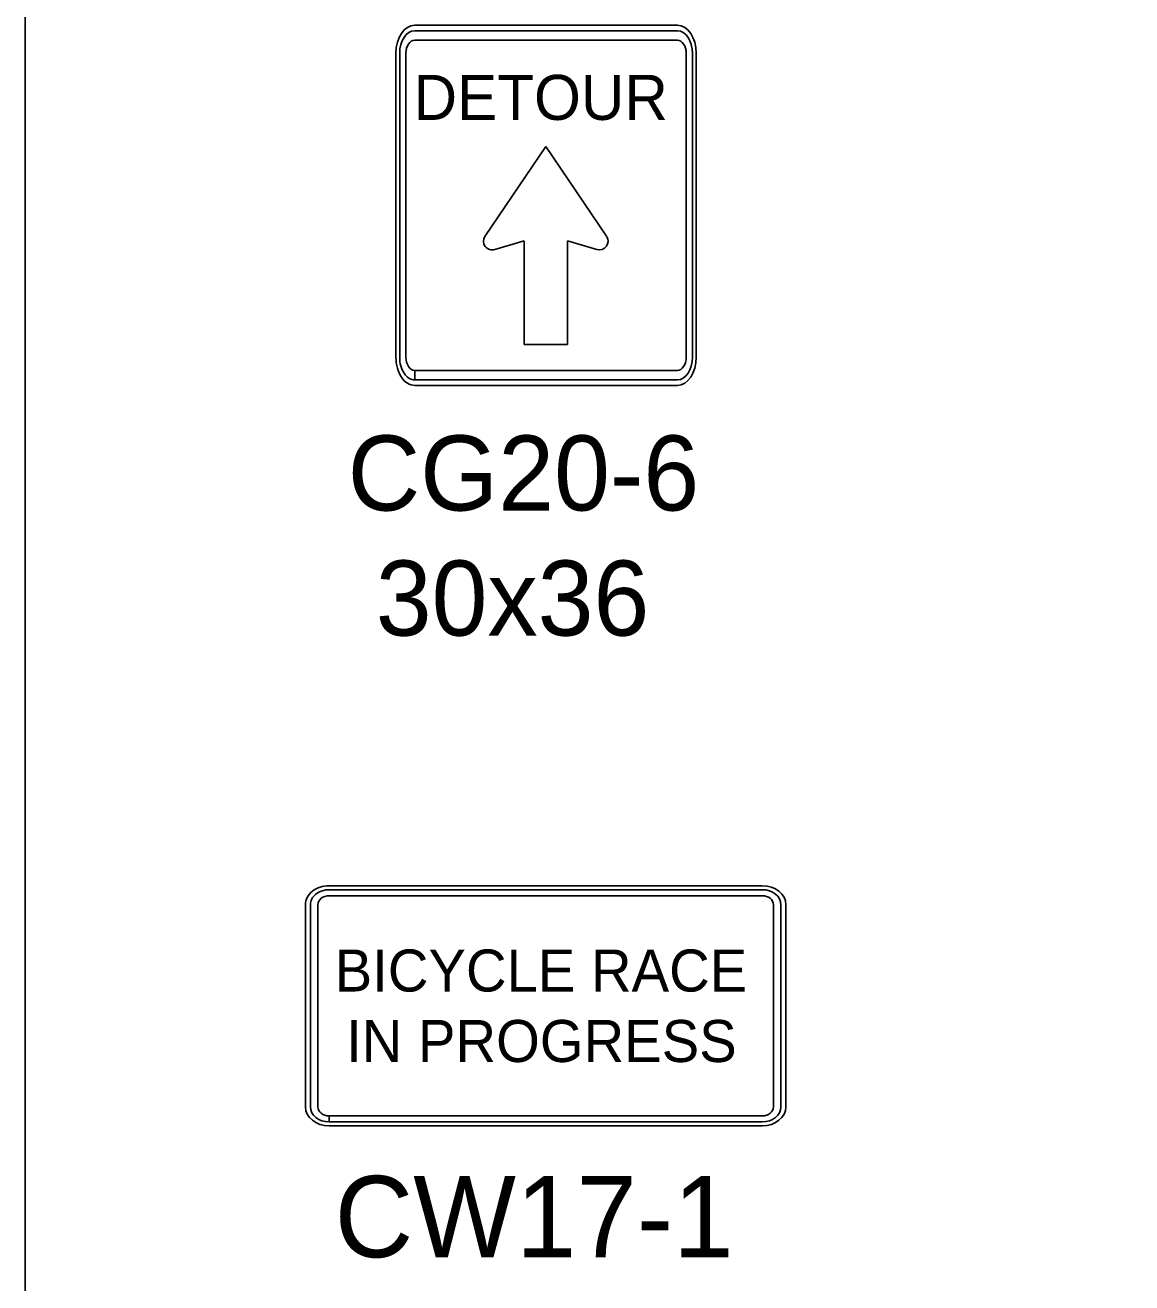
# Model space of a CAD drawing. Extents: x 1458 to 4498, y 17709 to 24109.
# Drawn here: x 1458.4 to 1679.5, y 21192.9 to 21444.2 of the extents above; entities that cross this region are included whole.
import ezdxf

# ---------------------------------------------------------------- set-up
doc = ezdxf.new("R2010")
doc.units = 0
doc.layers.add('P_TRAF_TCP_General', color=7, linetype='Continuous')

msp = doc.modelspace()

# ---------------------------------------------------------------- linework, layer by layer
at = {"layer": 'P_TRAF_TCP_General'}
for p, q in [((1588.72, 21444.19), (1536.24, 21444.19)), ((1588.72, 21443.06), (1536.24, 21443.06)), ((1588.72, 21443.06), (1536.24, 21443.06)), ((1536.24, 21441.19), (1588.72, 21441.19)), ((1532.49, 21438.57), (1532.49, 21377.84)), ((1533.24, 21438.57), (1533.24, 21377.84)), ((1533.24, 21438.57), (1533.24, 21377.84)), ((1534.49, 21377.84), (1534.49, 21438.57)), ((1590.47, 21438.57), (1590.47, 21377.84)), ((1591.72, 21377.84), (1591.72, 21438.57)), ((1591.72, 21377.84), (1591.72, 21438.57)), ((1592.47, 21377.84), (1592.47, 21438.57)), ((1562.41, 21419.94), (1550.25, 21401.99)), ((1574.56, 21402.01), (1562.41, 21419.94)), ((1552.24, 21399.39), (1558.09, 21401.08)), ((1558.09, 21401.08), (1558.09, 21380.36)), ((1566.73, 21380.36), (1566.73, 21401.08)), ((1566.73, 21401.08), (1572.64, 21399.37)), ((1536.24, 21373.34), (1536.24, 21375.22)), ((1588.72, 21375.22), (1536.25, 21375.22)), ((1536.25, 21375.22), (1536.25, 21373.34)), ((1536.24, 21373.34), (1588.72, 21373.34)), ((1536.24, 21372.22), (1588.72, 21372.22)), ((1536.25, 21373.34), (1588.72, 21373.34)), ((1605.64, 21272.28), (1519.17, 21272.28)), ((1605.64, 21271.48), (1519.17, 21271.48)), ((1514.42, 21268.48), (1514.42, 21228.09)), ((1515.42, 21268.48), (1515.42, 21228.09)), ((1516.92, 21268.48), (1516.92, 21228.09)), ((1516.92, 21228.09), (1516.92, 21268.48)), ((1605.64, 21270.28), (1519.17, 21270.28)), ((1519.17, 21270.28), (1605.64, 21270.28)), ((1607.89, 21228.09), (1607.89, 21268.48)), ((1607.89, 21268.48), (1607.89, 21228.09)), ((1609.39, 21228.09), (1609.39, 21268.48)), ((1610.39, 21228.09), (1610.39, 21268.48)), ((1519.17, 21226.29), (1605.64, 21226.29)), ((1519.17, 21225.1), (1519.17, 21226.29)), ((1605.64, 21226.29), (1519.19, 21226.29)), ((1519.19, 21226.29), (1519.19, 21225.1)), ((1519.17, 21224.3), (1605.64, 21224.3)), ((1519.19, 21225.1), (1605.64, 21225.1))]:
    msp.add_line(p, q, dxfattribs=at)
msp.add_lwpolyline([(4498.44, 21909.14), (1458.44, 21909.14), (1458.44, 19909.14), (4498.44, 19909.14)], close=True, dxfattribs=at)
msp.add_lwpolyline([(1558.09, 21380.36), (1566.73, 21380.36)], dxfattribs=at)
for centre, start, end in [((1551.7, 21401.03), 146.7042, 288.0653), ((1573.13, 21401.03), 253.8223, 34.1163)]:
    msp.add_arc(centre, 1.73, start, end, dxfattribs=at)
for centre, major_axis, ratio, start_param, end_param in [((1536.24, 21438.57), (0, 5.62), 0.666667, 0, 1.570796), ((1536.24, 21438.57), (0, 4.5), 0.666667, 0, 1.570796), ((1536.24, 21438.57), (0, 4.5), 0.666667, 0, 1.570796), ((1588.72, 21438.57), (0, 5.62), 0.666667, 4.712389, 6.283185), ((1588.72, 21438.57), (0, 4.5), 0.666667, 4.712389, 6.283185), ((1588.72, 21438.57), (0, 4.5), 0.666667, 4.712389, 6.283185), ((1536.24, 21438.57), (0, 2.62), 0.666667, 0, 1.570796), ((1588.72, 21438.57), (0, 2.62), 0.666667, 4.712389, 6.283185), ((1536.24, 21377.84), (0, 5.62), 0.666667, 1.570796, 3.141593), ((1536.24, 21377.84), (0, 4.5), 0.666667, 1.570796, 3.141593), ((1536.24, 21377.84), (0, 4.5), 0.666667, 1.570796, 3.141593), ((1536.24, 21377.84), (0, 2.62), 0.666667, 1.570796, 3.141593), ((1588.72, 21377.84), (0, 4.5), 0.666667, 3.141593, 4.712389), ((1588.72, 21377.84), (0, 4.5), 0.666667, 3.141593, 4.712389), ((1588.72, 21377.84), (0, 2.62), 0.666667, 3.141593, 4.712389), ((1588.72, 21377.84), (0, 5.62), 0.666667, 3.141593, 4.712389), ((1519.17, 21268.48), (4.75, 0), 0.8, 1.570796, 3.141593), ((1519.17, 21268.48), (3.75, 0), 0.8, 1.570796, 3.141593), ((1605.64, 21268.48), (4.75, 0), 0.8, 0, 1.570796), ((1605.64, 21268.48), (3.75, 0), 0.8, 0, 1.570796), ((1519.17, 21268.48), (2.25, 0), 0.8, 1.570796, 3.141593), ((1519.17, 21268.48), (2.25, 0), 0.8, 1.570796, 3.141593), ((1605.64, 21268.48), (2.25, 0), 0.8, 0, 1.570796), ((1605.64, 21268.48), (2.25, 0), 0.8, 0, 1.570796), ((1519.17, 21228.09), (4.75, 0), 0.8, 3.141593, 4.712389), ((1519.17, 21228.09), (3.75, 0), 0.8, 3.141593, 4.712389), ((1519.17, 21228.09), (2.25, 0), 0.8, 3.141593, 4.712389), ((1519.17, 21228.09), (2.25, 0), 0.8, 3.141593, 4.712389), ((1605.64, 21228.09), (2.25, 0), 0.8, 4.712389, 6.283185), ((1605.64, 21228.09), (3.75, 0), 0.8, 4.712389, 6.283185), ((1605.64, 21228.09), (2.25, 0), 0.8, 4.712389, 6.283185), ((1605.64, 21228.09), (4.75, 0), 0.8, 4.712389, 6.283185)]:
    msp.add_ellipse(centre, major_axis=major_axis, ratio=ratio, start_param=start_param, end_param=end_param, dxfattribs=at)

# ---------------------------------------------------------------- texts
for s, height, p in [('DETOUR', 8.996, (1536.02, 21425.26)), ('CG20-6', 14.994, (1522.86, 21347.23)), ('30x36', 14.994, (1528.47, 21322.24)), ('BICYCLE RACE', 8.4, (1520.26, 21251.13)), ('IN PROGRESS', 8.4, (1522.54, 21237.05)), ('CW17-1', 16.25, (1520.25, 21198.05))]:
    msp.add_text(s, height=height, dxfattribs=at).set_placement(p)

doc.saveas('drawing.dxf')
